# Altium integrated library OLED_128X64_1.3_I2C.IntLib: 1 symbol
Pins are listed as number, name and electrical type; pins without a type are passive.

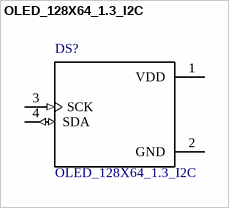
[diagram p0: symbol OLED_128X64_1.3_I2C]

## OLED_128X64_1.3_I2C
designator DS?
Non-Touch Graphic LCD Display Module Transmissive White OLED, Monochrome I2C 1.3 (33.02mm) 128 x 64; MF: UNIVERSAL-SOLDER Electronics Ltd; MP: OLED 128x64 1.3&quot; I2C
footprint *LCD_OLED_128X64_1.3_I2C
pins: 1 VDD (power), 2 GND (power), 3 SCK (in), 4 SDA (io)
